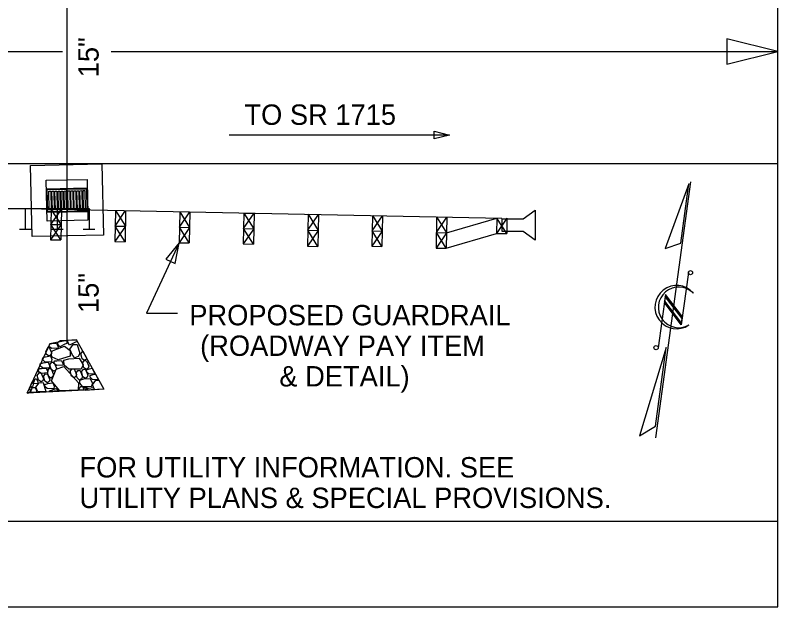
# Model space of a CAD drawing. Extents: x 985 to 1514, y -701 to -21.
# Drawn here: x 1168.3 to 1243.1, y -465.7 to -407.6 of the extents above; entities that cross this region are included whole.
import ezdxf

# ---------------------------------------------------------------- set-up
doc = ezdxf.new("R2010")
doc.units = 0
for name, color, linetype in [('Arrowhead Terminators CELL', 7, 'Continuous'), ('Default', 7, 'Continuous'), ('Dimension Lines', 7, 'Continuous'), ('Plan Sheet CELL', 7, 'Continuous'), ('Prop EOT', 7, 'Continuous'), ('Prop Horizontal Alignment', 7, 'Continuous'), ('Sheet North Arrow CELL', 7, 'Continuous'), ('Sup Concrete Girder Lines', 7, 'Continuous'), ('Text', 7, 'Continuous')]:
    doc.layers.add(name, color=color, linetype=linetype)

msp = doc.modelspace()

# ---------------------------------------------------------------- linework, layer by layer
at = {"layer": 'Arrowhead Terminators CELL'}
for points in [[(1243.069, -411.175), (1238.069, -409.925), (1238.069, -412.425)], [(1210.876, -419.368), (1209.376, -419.743), (1209.376, -418.993)], [(1210.876, -419.368), (1209.376, -419.743), (1209.376, -418.993)], [(1184.354, -429.941), (1183.063, -431.549), (1183.972, -431.967)]]:
    msp.add_lwpolyline(points, close=True, dxfattribs=at)
at = {"layer": 'Default'}
for p, q in [((1173.344, -424.6), (1173.344, -424.6)), ((1171.37, -425.809), (1171.37, -425.809)), ((1173.369, -425.766), (1173.369, -425.766)), ((1175.369, -425.723), (1175.369, -425.723)), ((1156.773, -426.592), (1175.523, -426.592)), ((1169.273, -426.592), (1169.273, -428.592)), ((1169.273, -426.592), (1216.015, -427.526)), ((1171.815, -426.642), (1171.755, -429.641)), ((1171.785, -428.142), (1172.815, -426.662)), ((1171.815, -426.642), (1172.815, -426.662)), ((1172.785, -428.162), (1171.815, -426.642)), ((1172.398, -426.592), (1172.398, -428.592)), ((1172.815, -426.662), (1172.755, -429.661)), ((1172.815, -426.662), (1172.785, -428.162)), ((1173.394, -426.932), (1173.394, -426.932)), ((1175.523, -426.592), (1175.523, -428.592)), ((1178.115, -426.768), (1178.054, -429.82)), ((1178.085, -428.294), (1179.115, -426.788)), ((1178.115, -426.768), (1179.085, -428.314)), ((1179.115, -426.788), (1179.054, -429.84)), ((1184.415, -426.894), (1184.354, -429.941)), ((1184.385, -428.418), (1185.415, -426.914)), ((1184.415, -426.894), (1185.385, -428.438)), ((1185.415, -426.914), (1185.354, -429.961)), ((1218.093, -427.606), (1219.27, -426.747)), ((1219.27, -426.747), (1219.266, -429.687)), ((1190.715, -427.02), (1190.654, -430.055)), ((1190.685, -428.538), (1191.715, -427.04)), ((1190.715, -427.02), (1191.715, -427.04)), ((1190.715, -427.02), (1191.685, -428.558)), ((1191.715, -427.04), (1191.654, -430.075)), ((1197.015, -427.146), (1196.952, -430.283)), ((1196.983, -428.714), (1198.015, -427.166)), ((1197.015, -427.146), (1197.983, -428.734)), ((1198.015, -427.166), (1197.952, -430.303)), ((1203.315, -427.272), (1203.255, -430.271)), ((1203.285, -428.772), (1204.315, -427.292)), ((1203.315, -427.272), (1204.285, -428.792)), ((1204.315, -427.292), (1204.255, -430.291)), ((1209.615, -427.398), (1209.554, -430.461)), ((1209.585, -428.93), (1210.615, -427.418)), ((1209.615, -427.398), (1210.585, -428.95)), ((1210.615, -427.418), (1210.554, -430.481)), ((1210.585, -428.95), (1215.515, -427.516)), ((1215.515, -427.516), (1215.485, -429.016)), ((1216.515, -427.536), (1215.485, -429.016)), ((1216.485, -429.036), (1215.515, -427.516)), ((1216.044, -428.213), (1216.046, -427.602)), ((1216.046, -427.602), (1218.093, -427.606)), ((1216.515, -427.536), (1216.485, -429.036)), ((1172.785, -428.162), (1171.755, -429.641)), ((1171.785, -428.142), (1172.785, -428.162)), ((1172.755, -429.661), (1171.785, -428.142)), ((1179.085, -428.314), (1178.054, -429.82)), ((1178.085, -428.294), (1179.085, -428.314)), ((1179.054, -429.84), (1178.085, -428.294)), ((1185.385, -428.438), (1184.354, -429.941)), ((1184.385, -428.418), (1185.385, -428.438)), ((1185.354, -429.961), (1184.385, -428.418)), ((1216.042, -428.824), (1216.044, -428.213)), ((1168.7, -428.592), (1169.846, -428.592)), ((1171.825, -428.592), (1172.971, -428.592)), ((1174.95, -428.592), (1176.096, -428.592)), ((1191.685, -428.558), (1190.654, -430.055)), ((1190.685, -428.538), (1191.685, -428.558)), ((1191.654, -430.075), (1190.685, -428.538)), ((1197.983, -428.734), (1196.952, -430.283)), ((1196.983, -428.714), (1197.983, -428.734)), ((1197.952, -430.303), (1196.983, -428.714)), ((1204.285, -428.792), (1203.255, -430.271)), ((1203.285, -428.772), (1204.285, -428.792)), ((1204.255, -430.291), (1203.285, -428.772)), ((1210.585, -428.95), (1209.554, -430.461)), ((1209.585, -428.93), (1210.585, -428.95)), ((1210.554, -430.481), (1209.585, -428.93)), ((1210.554, -430.481), (1215.485, -429.016)), ((1215.485, -429.016), (1215.985, -429.026)), ((1215.485, -429.016), (1216.485, -429.036)), ((1218.089, -428.828), (1216.042, -428.824)), ((1219.266, -429.687), (1218.089, -428.828)), ((1171.755, -429.641), (1172.755, -429.661)), ((1178.054, -429.82), (1179.054, -429.84)), ((1184.354, -429.941), (1185.354, -429.961)), ((1190.654, -430.055), (1191.654, -430.075)), ((1196.952, -430.283), (1197.952, -430.303)), ((1203.255, -430.271), (1204.255, -430.291)), ((1209.554, -430.461), (1210.554, -430.481)), ((1172.726, -439.541), (1173.342, -439.512)), ((1173.342, -439.512), (1173.342, -439.512)), ((1173.441, -439.509), (1174.29, -439.472)), ((1174.356, -439.592), (1174.29, -439.472)), ((1171.478, -440.17), (1171.28, -440.613)), ((1170.954, -441.344), (1171.019, -441.199)), ((1171.887, -440.58), (1171.818, -440.919)), ((1174.91, -440.589), (1175.294, -441.28)), ((1171.524, -442.359), (1171.458, -442.681)), ((1176.136, -442.804), (1175.837, -442.256)), ((1170.054, -443.788), (1170.234, -443.284)), ((1176.474, -443.408), (1176.967, -444.287)), ((1169.466, -444.677), (1169.678, -444.201)), ((1169.737, -444.079), (1169.956, -443.577)), ((1169.931, -444.146), (1169.76, -444.633)), ((1175.34, -444.204), (1174.992, -444.219)), ((1171.273, -444.534), (1170.511, -444.567)), ((1172.599, -444.476), (1171.597, -444.52)), ((1174.445, -444.393), (1172.665, -444.471)), ((1175.017, -444.369), (1174.534, -444.39)), ((1175.16, -444.387), (1176.024, -444.349)), ((1176.07, -444.323), (1176.967, -444.284))]:
    msp.add_line(p, q, dxfattribs=at)
for points in [[(1169.795, -422.342), (1176.793, -422.192), (1176.943, -429.19), (1169.945, -429.34)], [(1171.327, -423.809), (1175.326, -423.723), (1175.412, -427.723), (1171.412, -427.808)]]:
    msp.add_lwpolyline(points, close=True, dxfattribs=at)
for points in [[(1171.345, -424.642), (1175.344, -424.557), (1175.394, -426.889), (1171.395, -426.975), (1171.345, -424.642)], [(1171.408, -424.704), (1175.282, -424.62), (1175.33, -426.828), (1171.456, -426.911), (1171.408, -424.704)], [(1171.419, -424.714), (1173.335, -424.673), (1173.382, -426.86), (1171.466, -426.901), (1171.419, -424.714)], [(1173.356, -424.672), (1175.272, -424.631), (1175.319, -426.818), (1173.403, -426.859), (1173.356, -424.672)], [(1171.59, -424.892), (1171.767, -424.889), (1171.806, -426.711), (1171.629, -426.715), (1171.59, -424.892)], [(1171.886, -424.886), (1172.063, -424.882), (1172.103, -426.705), (1171.925, -426.709), (1171.886, -424.886)], [(1172.183, -424.88), (1172.36, -424.876), (1172.399, -426.698), (1172.222, -426.702), (1172.183, -424.88)], [(1172.48, -424.873), (1172.657, -424.87), (1172.696, -426.692), (1172.519, -426.696), (1172.48, -424.873)], [(1172.777, -424.867), (1172.954, -424.863), (1172.993, -426.686), (1172.816, -426.689), (1172.777, -424.867)], [(1173.074, -424.861), (1173.251, -424.857), (1173.29, -426.679), (1173.113, -426.683), (1173.074, -424.861)], [(1173.448, -424.853), (1173.625, -424.849), (1173.665, -426.671), (1173.488, -426.675), (1173.448, -424.853)], [(1173.745, -424.846), (1173.922, -424.842), (1173.961, -426.665), (1173.784, -426.669), (1173.745, -424.846)], [(1174.042, -424.84), (1174.219, -424.836), (1174.258, -426.659), (1174.081, -426.662), (1174.042, -424.84)], [(1174.339, -424.833), (1174.516, -424.83), (1174.555, -426.652), (1174.378, -426.656), (1174.339, -424.833)], [(1174.636, -424.827), (1174.813, -424.823), (1174.852, -426.646), (1174.675, -426.65), (1174.636, -424.827)], [(1174.932, -424.821), (1175.109, -424.817), (1175.149, -426.639), (1174.971, -426.643), (1174.932, -424.821)], [(1173.353, -439.812), (1173.144, -439.897), (1172.667, -440.155), (1172.455, -439.877), (1172.447, -439.689), (1172.726, -439.541)], [(1173.34, -439.514), (1173.353, -439.812)], [(1174.358, -439.619), (1174.137, -439.716), (1173.623, -439.976), (1173.46, -439.683), (1173.441, -439.509)], [(1174.356, -439.592), (1174.358, -439.619)], [(1171.478, -440.17), (1171.614, -440.192), (1171.839, -440.745), (1171.784, -440.935), (1171.602, -441.055)], [(1171.665, -439.845), (1171.889, -439.822), (1172.338, -439.79), (1172.476, -440.084), (1172.484, -440.272), (1171.886, -440.31), (1171.577, -440.111), (1171.665, -439.845)], [(1171.887, -440.58), (1172.154, -440.44), (1173.114, -440.073), (1173.672, -440.524), (1173.658, -441.063), (1172.485, -441.427), (1171.898, -441.165), (1171.818, -440.919)], [(1174.116, -441.243), (1173.916, -440.952), (1173.653, -440.375), (1173.972, -439.936), (1174.371, -439.906), (1174.622, -440.796), (1174.448, -441.103), (1174.116, -441.243)], [(1171.019, -441.199), (1171.261, -441.117), (1171.746, -441.046), (1171.873, -441.378), (1171.822, -441.643), (1171.183, -441.608), (1170.949, -441.406), (1170.954, -441.344)], [(1171.602, -441.055), (1171.357, -440.891), (1171.28, -440.613)], [(1175.09, -441.478), (1174.845, -441.313), (1174.711, -440.831), (1174.91, -440.589)], [(1170.743, -441.82), (1171.039, -441.719), (1171.524, -441.648), (1171.651, -441.98), (1171.6, -442.245), (1170.961, -442.21), (1170.727, -442.008), (1170.743, -441.82)], [(1172.046, -442.547), (1171.814, -442.382), (1171.668, -441.9), (1171.883, -441.666), (1172.07, -441.658), (1172.32, -442.235), (1172.23, -442.464), (1172.046, -442.547)], [(1172.152, -441.529), (1172.376, -441.507), (1172.825, -441.475), (1172.963, -441.769), (1172.971, -441.956), (1172.372, -441.995), (1172.063, -441.796), (1172.152, -441.529)], [(1173.05, -441.465), (1173.531, -441.319), (1174.542, -441.25), (1174.934, -441.908), (1174.764, -442.328), (1173.526, -442.332), (1173.096, -441.938), (1173.05, -441.465)], [(1175.266, -442.371), (1175.022, -442.206), (1174.888, -441.724), (1175.09, -441.478), (1175.279, -441.507), (1175.503, -442.06), (1175.449, -442.25), (1175.266, -442.371)], [(1175.294, -441.28), (1175.272, -441.357), (1175.09, -441.478)], [(1170.815, -443.593), (1170.57, -443.428), (1170.437, -442.946), (1170.639, -442.7), (1170.827, -442.729), (1171.052, -443.282), (1170.998, -443.472), (1170.815, -443.593)], [(1170.631, -442.288), (1170.855, -442.266), (1171.304, -442.233), (1171.442, -442.528), (1171.45, -442.715), (1170.851, -442.754), (1170.542, -442.554), (1170.631, -442.288)], [(1171.762, -443.21), (1171.553, -442.994), (1171.458, -442.681)], [(1171.524, -442.359), (1171.584, -442.279), (1171.809, -442.27), (1172.036, -442.885), (1171.945, -443.089), (1171.762, -443.21)], [(1172.665, -444.471), (1171.836, -443.47), (1172.288, -442.349), (1173.064, -442.065), (1174.486, -443.692), (1174.445, -444.394)], [(1174.051, -443.185), (1173.818, -443.02), (1173.685, -442.538), (1173.874, -442.292), (1174.063, -442.321), (1174.3, -442.874), (1174.233, -443.065), (1174.051, -443.185)], [(1174.599, -443.412), (1174.364, -443.197), (1174.268, -442.725), (1174.433, -442.48), (1174.658, -442.471), (1174.885, -443.099), (1174.781, -443.291), (1174.599, -443.412)], [(1175.167, -443.249), (1174.922, -443.085), (1174.789, -442.603), (1174.991, -442.356), (1175.18, -442.385), (1175.404, -442.939), (1175.35, -443.129), (1175.167, -443.249)], [(1176.136, -442.804), (1176.132, -442.821), (1175.493, -442.787), (1175.259, -442.584), (1175.275, -442.396)], [(1175.275, -442.396), (1175.571, -442.295), (1175.837, -442.256)], [(1170.232, -443.287), (1170.357, -443.278), (1170.495, -443.572), (1170.503, -443.76), (1170.056, -443.788)], [(1171.436, -443.682), (1171.191, -443.517), (1171.057, -443.035), (1171.259, -442.788), (1171.448, -442.818), (1171.673, -443.371), (1171.618, -443.561), (1171.436, -443.682)], [(1174.625, -443.436), (1175.019, -443.293), (1175.618, -443.255), (1175.877, -443.756), (1175.741, -444.075), (1174.876, -444.038), (1174.637, -443.723), (1174.625, -443.436)], [(1176.459, -443.373), (1175.862, -443.341), (1175.628, -443.138), (1175.645, -442.95)], [(1175.645, -442.95), (1175.941, -442.849), (1176.143, -442.82)], [(1176.07, -444.323), (1175.863, -443.869), (1176.182, -443.43), (1176.476, -443.408)], [(1176.142, -442.82), (1176.143, -442.82), (1176.457, -443.372)], [(1169.678, -444.2), (1169.76, -444.403), (1169.706, -444.593), (1169.523, -444.714)], [(1169.821, -444.133), (1169.734, -444.075)], [(1169.931, -444.146), (1170.241, -444.124), (1170.379, -444.418), (1170.387, -444.605), (1169.788, -444.644), (1169.76, -444.633)], [(1169.957, -443.575), (1170.057, -443.822), (1170.003, -444.013), (1169.821, -444.133)], [(1170.514, -444.565), (1170.307, -444.111), (1170.626, -443.672), (1171.025, -443.642), (1171.277, -444.532)], [(1171.203, -443.86), (1171.498, -443.76), (1171.983, -443.688), (1172.11, -444.021), (1172.059, -444.286), (1171.42, -444.251), (1171.186, -444.048), (1171.203, -443.86)], [(1174.534, -444.39), (1174.508, -444.295), (1174.71, -444.049), (1174.899, -444.078), (1175.017, -444.369)], [(1174.992, -444.219), (1175.108, -444.077), (1175.297, -444.106), (1175.34, -444.204)], [(1175.166, -444.32), (1175.462, -444.219), (1175.947, -444.148), (1176.024, -444.349)], [(1169.523, -444.714), (1169.465, -444.675)], [(1171.597, -444.518), (1171.642, -444.479), (1172.307, -444.237), (1172.599, -444.474)], [(1175.16, -444.387), (1175.166, -444.32)]]:
    msp.add_lwpolyline(points, dxfattribs=at)
at = {"layer": 'Dimension Lines'}
for p, q in [((1210.876, -419.368), (1189.258, -419.368)), ((1184.354, -429.941), (1181.171, -436.854)), ((1181.171, -436.854), (1184.205, -436.854))]:
    msp.add_line(p, q, dxfattribs=at)
at = {"layer": 'Plan Sheet CELL'}
msp.add_line((1002.096, -457.245), (1243.069, -457.245), dxfattribs=at)
msp.add_lwpolyline([(1002.096, -465.652), (1243.069, -465.652), (1243.069, -355.46)], dxfattribs=at)
at = {"layer": 'Prop EOT'}
msp.add_line((1002.096, -422.175), (1243.069, -422.175), dxfattribs=at)
at = {"layer": 'Prop Horizontal Alignment'}
for p, q in [((1002.096, -411.175), (1172.926, -411.175)), ((1177.698, -411.175), (1243.069, -411.175))]:
    msp.add_line(p, q, dxfattribs=at)
at = {"layer": 'Sheet North Arrow CELL'}
for p, q in [((1231.125, -449.089), (1234.555, -423.972)), ((1234.308, -432.842), (1233.604, -437.996)), ((1232.056, -435.01), (1231.34, -440.25)), ((1232.03, -435.199), (1231.965, -435.671)), ((1233.688, -437.382), (1232.03, -435.199)), ((1233.714, -437.193), (1232.056, -435.01)), ((1234.757, -434.859), (1234.781, -434.882)), ((1233.604, -437.996), (1231.946, -435.814)), ((1233.623, -437.853), (1231.965, -435.671)), ((1231.965, -435.671), (1233.623, -437.853)), ((1233.623, -437.853), (1233.688, -437.382))]:
    msp.add_line(p, q, dxfattribs=at)
for points in [[(1234.351, -424.168), (1232.027, -430.495), (1233.559, -429.964)], [(1232.128, -440.212), (1229.498, -448.866), (1231.073, -447.94)]]:
    msp.add_lwpolyline(points, close=True, dxfattribs=at)
for centre in [(1234.512, -432.874), (1231.134, -440.229)]:
    msp.add_circle(centre, 0.207, dxfattribs=at)
for centre, radius, start, end in [((1233.15, -436.252), 2.129, 40.06351, 304.61755), ((1233.354, -436.279), 1.996, 45.31853, 300.8522)]:
    msp.add_arc(centre, radius, start, end, dxfattribs=at)
at = {"layer": 'Sup Concrete Girder Lines'}
for p, q in [((1173.347, -400.76), (1173.342, -439.513)), ((1173.344, -424.6), (1173.344, -424.6)), ((1171.37, -425.809), (1171.37, -425.809)), ((1173.369, -425.766), (1173.369, -425.766)), ((1175.369, -425.723), (1175.369, -425.723)), ((1173.394, -426.932), (1173.394, -426.932)), ((1173.342, -439.512), (1171.665, -439.845)), ((1172.726, -439.541), (1173.342, -439.512)), ((1174.29, -439.472), (1173.342, -439.513)), ((1173.342, -439.512), (1173.342, -439.512)), ((1173.441, -439.509), (1174.29, -439.472)), ((1174.356, -439.592), (1174.29, -439.472)), ((1176.967, -444.284), (1174.29, -439.472)), ((1171.665, -439.845), (1169.466, -444.677)), ((1171.478, -440.17), (1171.28, -440.613)), ((1170.954, -441.344), (1171.019, -441.199)), ((1171.887, -440.58), (1171.818, -440.919)), ((1174.91, -440.589), (1175.294, -441.28)), ((1171.524, -442.359), (1171.458, -442.681)), ((1176.136, -442.804), (1175.837, -442.256)), ((1170.054, -443.788), (1170.234, -443.284)), ((1176.474, -443.408), (1176.967, -444.287)), ((1169.466, -444.677), (1169.678, -444.201)), ((1169.737, -444.079), (1169.956, -443.577)), ((1169.931, -444.146), (1169.76, -444.633)), ((1175.34, -444.204), (1174.992, -444.219)), ((1169.466, -444.677), (1176.967, -444.284)), ((1169.466, -444.677), (1176.967, -444.284)), ((1171.273, -444.534), (1170.511, -444.567)), ((1172.599, -444.476), (1171.597, -444.52)), ((1174.445, -444.393), (1172.665, -444.471)), ((1175.017, -444.369), (1174.534, -444.39)), ((1175.16, -444.387), (1176.024, -444.349)), ((1176.07, -444.323), (1176.967, -444.284))]:
    msp.add_line(p, q, dxfattribs=at)
for points in [[(1169.795, -422.342), (1176.793, -422.192), (1176.943, -429.19), (1169.945, -429.34)], [(1171.327, -423.809), (1175.326, -423.723), (1175.412, -427.723), (1171.412, -427.808)]]:
    msp.add_lwpolyline(points, close=True, dxfattribs=at)
for points in [[(1171.345, -424.642), (1175.344, -424.557), (1175.394, -426.889), (1171.395, -426.975), (1171.345, -424.642)], [(1171.408, -424.704), (1175.282, -424.62), (1175.33, -426.828), (1171.456, -426.911), (1171.408, -424.704)], [(1171.419, -424.714), (1173.335, -424.673), (1173.382, -426.86), (1171.466, -426.901), (1171.419, -424.714)], [(1173.356, -424.672), (1175.272, -424.631), (1175.319, -426.818), (1173.403, -426.859), (1173.356, -424.672)], [(1171.59, -424.892), (1171.767, -424.889), (1171.806, -426.711), (1171.629, -426.715), (1171.59, -424.892)], [(1171.886, -424.886), (1172.063, -424.882), (1172.103, -426.705), (1171.925, -426.709), (1171.886, -424.886)], [(1172.183, -424.88), (1172.36, -424.876), (1172.399, -426.698), (1172.222, -426.702), (1172.183, -424.88)], [(1172.48, -424.873), (1172.657, -424.87), (1172.696, -426.692), (1172.519, -426.696), (1172.48, -424.873)], [(1172.777, -424.867), (1172.954, -424.863), (1172.993, -426.686), (1172.816, -426.689), (1172.777, -424.867)], [(1173.074, -424.861), (1173.251, -424.857), (1173.29, -426.679), (1173.113, -426.683), (1173.074, -424.861)], [(1173.448, -424.853), (1173.625, -424.849), (1173.665, -426.671), (1173.488, -426.675), (1173.448, -424.853)], [(1173.745, -424.846), (1173.922, -424.842), (1173.961, -426.665), (1173.784, -426.669), (1173.745, -424.846)], [(1174.042, -424.84), (1174.219, -424.836), (1174.258, -426.659), (1174.081, -426.662), (1174.042, -424.84)], [(1174.339, -424.833), (1174.516, -424.83), (1174.555, -426.652), (1174.378, -426.656), (1174.339, -424.833)], [(1174.636, -424.827), (1174.813, -424.823), (1174.852, -426.646), (1174.675, -426.65), (1174.636, -424.827)], [(1174.932, -424.821), (1175.109, -424.817), (1175.149, -426.639), (1174.971, -426.643), (1174.932, -424.821)], [(1173.353, -439.812), (1173.144, -439.897), (1172.667, -440.155), (1172.455, -439.877), (1172.447, -439.689), (1172.726, -439.541)], [(1173.34, -439.514), (1173.353, -439.812)], [(1174.358, -439.619), (1174.137, -439.716), (1173.623, -439.976), (1173.46, -439.683), (1173.441, -439.509)], [(1174.356, -439.592), (1174.358, -439.619)], [(1171.478, -440.17), (1171.614, -440.192), (1171.839, -440.745), (1171.784, -440.935), (1171.602, -441.055)], [(1171.665, -439.845), (1171.889, -439.822), (1172.338, -439.79), (1172.476, -440.084), (1172.484, -440.272), (1171.886, -440.31), (1171.577, -440.111), (1171.665, -439.845)], [(1171.887, -440.58), (1172.154, -440.44), (1173.114, -440.073), (1173.672, -440.524), (1173.658, -441.063), (1172.485, -441.427), (1171.898, -441.165), (1171.818, -440.919)], [(1174.116, -441.243), (1173.916, -440.952), (1173.653, -440.375), (1173.972, -439.936), (1174.371, -439.906), (1174.622, -440.796), (1174.448, -441.103), (1174.116, -441.243)], [(1171.019, -441.199), (1171.261, -441.117), (1171.746, -441.046), (1171.873, -441.378), (1171.822, -441.643), (1171.183, -441.608), (1170.949, -441.406), (1170.954, -441.344)], [(1171.602, -441.055), (1171.357, -440.891), (1171.28, -440.613)], [(1175.09, -441.478), (1174.845, -441.313), (1174.711, -440.831), (1174.91, -440.589)], [(1170.743, -441.82), (1171.039, -441.719), (1171.524, -441.648), (1171.651, -441.98), (1171.6, -442.245), (1170.961, -442.21), (1170.727, -442.008), (1170.743, -441.82)], [(1172.046, -442.547), (1171.814, -442.382), (1171.668, -441.9), (1171.883, -441.666), (1172.07, -441.658), (1172.32, -442.235), (1172.23, -442.464), (1172.046, -442.547)], [(1172.152, -441.529), (1172.376, -441.507), (1172.825, -441.475), (1172.963, -441.769), (1172.971, -441.956), (1172.372, -441.995), (1172.063, -441.796), (1172.152, -441.529)], [(1173.05, -441.465), (1173.531, -441.319), (1174.542, -441.25), (1174.934, -441.908), (1174.764, -442.328), (1173.526, -442.332), (1173.096, -441.938), (1173.05, -441.465)], [(1175.266, -442.371), (1175.022, -442.206), (1174.888, -441.724), (1175.09, -441.478), (1175.279, -441.507), (1175.503, -442.06), (1175.449, -442.25), (1175.266, -442.371)], [(1175.294, -441.28), (1175.272, -441.357), (1175.09, -441.478)], [(1170.815, -443.593), (1170.57, -443.428), (1170.437, -442.946), (1170.639, -442.7), (1170.827, -442.729), (1171.052, -443.282), (1170.998, -443.472), (1170.815, -443.593)], [(1170.631, -442.288), (1170.855, -442.266), (1171.304, -442.233), (1171.442, -442.528), (1171.45, -442.715), (1170.851, -442.754), (1170.542, -442.554), (1170.631, -442.288)], [(1171.762, -443.21), (1171.553, -442.994), (1171.458, -442.681)], [(1171.524, -442.359), (1171.584, -442.279), (1171.809, -442.27), (1172.036, -442.885), (1171.945, -443.089), (1171.762, -443.21)], [(1172.665, -444.471), (1171.836, -443.47), (1172.288, -442.349), (1173.064, -442.065), (1174.486, -443.692), (1174.445, -444.394)], [(1174.051, -443.185), (1173.818, -443.02), (1173.685, -442.538), (1173.874, -442.292), (1174.063, -442.321), (1174.3, -442.874), (1174.233, -443.065), (1174.051, -443.185)], [(1174.599, -443.412), (1174.364, -443.197), (1174.268, -442.725), (1174.433, -442.48), (1174.658, -442.471), (1174.885, -443.099), (1174.781, -443.291), (1174.599, -443.412)], [(1175.167, -443.249), (1174.922, -443.085), (1174.789, -442.603), (1174.991, -442.356), (1175.18, -442.385), (1175.404, -442.939), (1175.35, -443.129), (1175.167, -443.249)], [(1176.136, -442.804), (1176.132, -442.821), (1175.493, -442.787), (1175.259, -442.584), (1175.275, -442.396)], [(1175.275, -442.396), (1175.571, -442.295), (1175.837, -442.256)], [(1170.232, -443.287), (1170.357, -443.278), (1170.495, -443.572), (1170.503, -443.76), (1170.056, -443.788)], [(1171.436, -443.682), (1171.191, -443.517), (1171.057, -443.035), (1171.259, -442.788), (1171.448, -442.818), (1171.673, -443.371), (1171.618, -443.561), (1171.436, -443.682)], [(1174.625, -443.436), (1175.019, -443.293), (1175.618, -443.255), (1175.877, -443.756), (1175.741, -444.075), (1174.876, -444.038), (1174.637, -443.723), (1174.625, -443.436)], [(1176.459, -443.373), (1175.862, -443.341), (1175.628, -443.138), (1175.645, -442.95)], [(1175.645, -442.95), (1175.941, -442.849), (1176.143, -442.82)], [(1176.07, -444.323), (1175.863, -443.869), (1176.182, -443.43), (1176.476, -443.408)], [(1176.142, -442.82), (1176.143, -442.82), (1176.457, -443.372)], [(1169.678, -444.2), (1169.76, -444.403), (1169.706, -444.593), (1169.523, -444.714)], [(1169.821, -444.133), (1169.734, -444.075)], [(1169.931, -444.146), (1170.241, -444.124), (1170.379, -444.418), (1170.387, -444.605), (1169.788, -444.644), (1169.76, -444.633)], [(1169.957, -443.575), (1170.057, -443.822), (1170.003, -444.013), (1169.821, -444.133)], [(1170.514, -444.565), (1170.307, -444.111), (1170.626, -443.672), (1171.025, -443.642), (1171.277, -444.532)], [(1171.203, -443.86), (1171.498, -443.76), (1171.983, -443.688), (1172.11, -444.021), (1172.059, -444.286), (1171.42, -444.251), (1171.186, -444.048), (1171.203, -443.86)], [(1174.534, -444.39), (1174.508, -444.295), (1174.71, -444.049), (1174.899, -444.078), (1175.017, -444.369)], [(1174.992, -444.219), (1175.108, -444.077), (1175.297, -444.106), (1175.34, -444.204)], [(1175.166, -444.32), (1175.462, -444.219), (1175.947, -444.148), (1176.024, -444.349)], [(1169.523, -444.714), (1169.465, -444.675)], [(1171.597, -444.518), (1171.642, -444.479), (1172.307, -444.237), (1172.599, -444.474)], [(1175.16, -444.387), (1175.166, -444.32)]]:
    msp.add_lwpolyline(points, dxfattribs=at)

# ---------------------------------------------------------------- texts
at = {"layer": 'Text'}
for p in [(1176.463, -413.698), (1176.463, -436.83)]:
    msp.add_text('15"', height=2, rotation=90, dxfattribs=at).set_placement(p)
for s, p in [('TO SR 1715', (1190.765, -418.368)), ('PROPOSED GUARDRAIL', (1185.356, -438.038)), ('(ROADWAY PAY ITEM', (1186.418, -441.038)), ('& DETAIL)', (1194.189, -444.038)), ('FOR UTILITY INFORMATION. SEE', (1174.588, -452.968)), ('UTILITY PLANS & SPECIAL PROVISIONS.', (1174.588, -455.968))]:
    msp.add_text(s, height=2, dxfattribs=at).set_placement(p)

doc.saveas('drawing.dxf')
